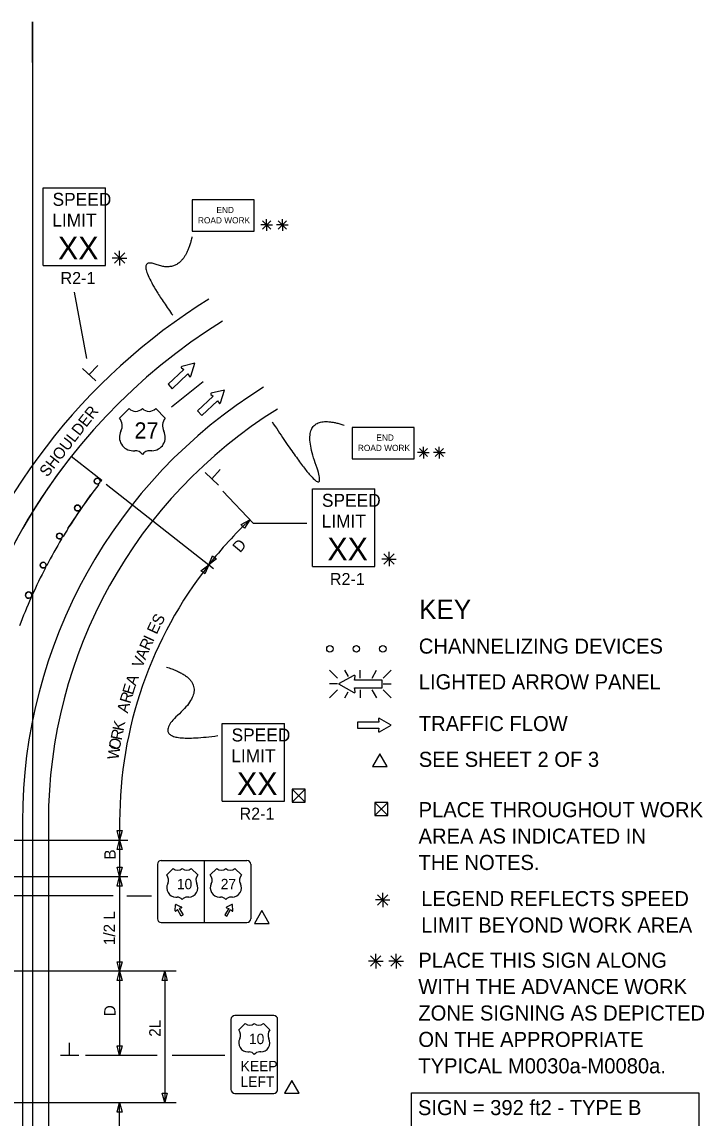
# Model space of a CAD drawing. Extents: x 16519 to 19508, y 5743 to 6974.
# Drawn here: x 16998 to 17419, y 6297 to 6974 of the extents above; entities that cross this region are included whole.
import ezdxf

# ---------------------------------------------------------------- set-up
doc = ezdxf.new("R2010")
doc.units = 0
for name, color, linetype in [('ALI_LEGAL_EX', 7, 'Continuous'), ('MT_SCRATCH_LEVEL_A', 7, 'Continuous'), ('MT_SCRATCH_LEVEL_E', 7, 'Continuous'), ('PAVT_EDGE_EX', 7, 'Continuous'), ('TRAFFIC_SIGNS_PR', 7, 'Continuous'), ('TYPICAL_EX', 7, 'Continuous'), ('TYPICAL_TEXT_DIMEN_EX', 7, 'Continuous'), ('TYPICAL_TEXT_DIMEN_PR', 7, 'Continuous')]:
    doc.layers.add(name, color=color, linetype=linetype)

msp = doc.modelspace()

# ---------------------------------------------------------------- linework, layer by layer
at = {"layer": 'ALI_LEGAL_EX'}
for p, q in [((17004.68, 6974.12), (17004.68, 6155.98)), ((17004.68, 6922.21), (17004.68, 6058.3))]:
    msp.add_line(p, q, dxfattribs=at)
for points in [[(17004.68, 6949.12), (17004.68, 6974.12)], [(17090.52, 6736.48), (17109.97, 6752.18)], [(17026.51, 6661.47), (17040.64, 6682.1)]]:
    msp.add_lwpolyline(points, dxfattribs=at)
at = {"layer": 'MT_SCRATCH_LEVEL_A'}
for points in [[(17047.4, 6690.98), (17028.55, 6705.83)], [(17045.52, 6688.56), (17045.06, 6688.91)], [(17046.41, 6690.77), (17047.26, 6690.79)], [(17033.55, 6672.09), (17033.12, 6672.38)], [(17034.27, 6674.06), (17034.69, 6673.76)], [(17022.59, 6654.94), (17022.2, 6655.17)], [(17023.15, 6656.76), (17023.54, 6656.52)], [(17013.08, 6638.82), (17013.44, 6638.63)], [(17012.67, 6637.16), (17012.32, 6637.35)], [(17003.81, 6618.76), (17003.65, 6618.83)], [(17004.31, 6620.31), (17004.48, 6620.24)]]:
    msp.add_lwpolyline(points, dxfattribs=at)
for centre, radius, start, end in [((17314.45, 6480.53), 364, 141.75977, 180), ((17044.61, 6690.66), 1.8, 3.5129, 180), ((17314.45, 6480.53), 340, 142.2759, 145.36613), ((17044.61, 6690.66), 1.8, 180, 284.5518), ((17314.45, 6480.53), 340, 141.75977, 141.79923), ((17314.45, 6480.53), 340, 145.70741, 148.82754), ((17032.47, 6674.06), 1.8, 0, 180), ((17032.47, 6674.06), 1.8, 180, 291.41483), ((17021.35, 6656.76), 1.8, 0, 180), ((17314.45, 6480.53), 340, 149.13833, 152.28953), ((17021.35, 6656.76), 1.8, 180, 298.27665), ((17011.28, 6638.82), 1.8, 0, 180), ((17011.28, 6638.82), 1.8, 180, 305.13736), ((17314.45, 6480.53), 340, 152.56868, 155.7382), ((17314.45, 6480.53), 340, 156.0121, 159.20322), ((17002.31, 6620.31), 2, 0, 180), ((17002.31, 6620.31), 2, 180, 312.02419)]:
    msp.add_arc(centre, radius, start, end, dxfattribs=at)
at = {"layer": 'MT_SCRATCH_LEVEL_E'}
for p, q in [((17096.59, 6760.6), (17098.04, 6759.51)), ((17104.85, 6763.37), (17096.76, 6761.41)), ((17102.41, 6755.39), (17104.85, 6763.37)), ((17098.04, 6759.51), (17088.37, 6750.45)), ((17090.92, 6747.72), (17100.6, 6756.78)), ((17100.6, 6756.78), (17101.58, 6755.27)), ((17088.37, 6750.45), (17090.92, 6747.72)), ((17123.06, 6746.9), (17114.96, 6744.94)), ((17120.61, 6738.92), (17123.06, 6746.9)), ((17116.24, 6743.04), (17106.57, 6733.98)), ((17109.13, 6731.25), (17118.8, 6740.31)), ((17114.79, 6744.12), (17116.24, 6743.04)), ((17118.8, 6740.31), (17119.78, 6738.8)), ((17106.57, 6733.98), (17109.13, 6731.25)), ((17218.08, 6543.71), (17218.4, 6541.94)), ((17226.01, 6540.09), (17218.77, 6544.2)), ((17218.4, 6541.94), (17205.14, 6541.94)), ((17205.14, 6541.94), (17205.14, 6538.19)), ((17205.14, 6538.19), (17218.4, 6538.19)), ((17218.4, 6538.19), (17218.08, 6536.42)), ((17218.77, 6535.94), (17226.01, 6540.09))]:
    msp.add_line(p, q, dxfattribs=at)
for centre, start, end in [((17096.87, 6760.96), 103.58205, 233.12102), ((17101.96, 6755.54), 213.1934, 342.93033), ((17115.08, 6744.49), 103.58205, 233.12102), ((17120.17, 6739.07), 213.1934, 342.93033), ((17218.54, 6543.79), 60.42484, 189.96381), ((17218.54, 6536.35), 170.03619, 299.77312)]:
    msp.add_arc(centre, 0.463, start, end, dxfattribs=at)
at = {"layer": 'PAVT_EDGE_EX'}
for p, q in [((16998.45, 6480.53), (16998.45, 6125.9)), ((17014.45, 6480.53), (17014.45, 6125.9))]:
    msp.add_line(p, q, dxfattribs=at)
for radius, start, end in [(380, 121.93275, 163.04831), (364, 121.93275, 180), (316, 121.93275, 180), (300, 121.93275, 180), (300, 180, 180.00000277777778)]:
    msp.add_arc((17314.45, 6480.53), radius, start, end, dxfattribs=at)
at = {"layer": 'TRAFFIC_SIGNS_PR'}
for p, q in [((17011.27, 6871.74), (17049.67, 6871.74)), ((17011.27, 6823.74), (17011.27, 6871.74)), ((17049.67, 6823.74), (17049.67, 6871.74)), ((17011.27, 6823.74), (17049.67, 6823.74)), ((17177.5, 6685.93), (17215.9, 6685.93)), ((17177.5, 6637.93), (17177.5, 6685.93)), ((17215.9, 6637.93), (17215.9, 6685.93)), ((17177.5, 6637.93), (17215.9, 6637.93)), ((17187.86, 6573.9), (17192.79, 6568.96)), ((17199.62, 6570.07), (17197.41, 6573.9)), ((17206.94, 6568.96), (17206.94, 6573.9)), ((17214.17, 6568.96), (17217.02, 6573.9)), ((17221.09, 6568.96), (17226.03, 6573.9)), ((17192.79, 6565.41), (17187.86, 6565.41)), ((17221.09, 6565.41), (17226.03, 6565.41)), ((17187.86, 6556.92), (17192.79, 6561.85)), ((17197.37, 6556.92), (17199.48, 6560.58)), ((17206.94, 6561.85), (17206.94, 6556.92)), ((17217.07, 6556.92), (17214.22, 6561.85)), ((17221.09, 6561.85), (17226.03, 6556.91)), ((17121.73, 6541.08), (17160.13, 6541.08)), ((17121.73, 6493.08), (17121.73, 6541.08)), ((17160.13, 6493.08), (17160.13, 6541.08)), ((17121.73, 6493.08), (17160.13, 6493.08)), ((17084.13, 6456.52), (17136.93, 6456.52)), ((17110.53, 6456.52), (17110.53, 6418.12)), ((17081.73, 6454.12), (17081.73, 6420.52)), ((17139.33, 6454.12), (17139.33, 6420.52)), ((17092.71, 6425.47), (17092.99, 6429.09)), ((17093.36, 6429.3), (17096.64, 6427.74)), ((17127.69, 6429.3), (17124.42, 6427.74)), ((17128.35, 6425.47), (17128.07, 6429.09)), ((17084.13, 6418.12), (17136.93, 6418.12)), ((17127.14, 6358.32), (17127.14, 6315.12)), ((17153.54, 6360.72), (17129.54, 6360.72)), ((17155.94, 6315.12), (17155.94, 6358.32)), ((17129.54, 6312.72), (17153.54, 6312.72))]:
    msp.add_line(p, q, dxfattribs=at)
for points in [[(17103.15, 6845), (17141.55, 6845), (17141.55, 6864.2), (17103.15, 6864.2)], [(17201.84, 6704.49), (17240.24, 6704.49), (17240.24, 6723.69), (17201.84, 6723.69)]]:
    msp.add_lwpolyline(points, close=True, dxfattribs=at)
for points in [[(17202.87, 6570.68), (17193.58, 6565.41), (17202.87, 6560.09)], [(17203.74, 6560.71), (17203.34, 6562.98), (17220.35, 6562.98), (17220.35, 6567.78), (17203.34, 6567.78), (17203.74, 6570.06)], [(17096.6, 6427.25), (17095.19, 6426.86), (17097.71, 6422.88), (17096.38, 6422.12), (17094.19, 6426.29), (17093.15, 6425.26)], [(17124.46, 6427.25), (17125.87, 6426.86), (17123.35, 6422.88), (17124.68, 6422.12), (17126.87, 6426.29), (17127.91, 6425.26)]]:
    msp.add_lwpolyline(points, dxfattribs=at)
for centre, radius in [((17044.61, 6690.66), 1.8), ((17032.47, 6674.06), 1.8), ((17021.35, 6656.76), 1.8), ((17011.28, 6638.82), 1.8), ((17002.31, 6620.31), 2), ((17188.2, 6587.09), 2), ((17204.5, 6587.09), 2), ((17220.8, 6587.09), 2)]:
    msp.add_circle(centre, radius, dxfattribs=at)
for centre, radius, start, end in [((17203.16, 6570.16), 0.598, 350.73078, 118.89165), ((17203.15, 6560.61), 0.597, 241.48329, 9.95933), ((17084.13, 6454.12), 2.4, 90, 180), ((17084.13, 6454.12), 2.4, 90, 180), ((17136.93, 6454.12), 2.4, 0, 90), ((17093.25, 6429.07), 0.26, 64.48226, 175.51774), ((17127.81, 6429.07), 0.26, 4.48226, 115.51774), ((17092.97, 6425.45), 0.26, 175.51775, 314.01151), ((17096.53, 6427.5), 0.26, 285.9885, 64.48226), ((17124.53, 6427.5), 0.26, 115.51774, 254.0115), ((17128.09, 6425.45), 0.26, 225.98849, 4.48225), ((17084.13, 6420.52), 2.4, 180, 270), ((17136.93, 6420.52), 2.4, 270, 0), ((17129.54, 6358.32), 2.4, 90, 180), ((17153.54, 6358.32), 2.4, 0, 90), ((17129.54, 6315.12), 2.4, 180, 270), ((17153.54, 6315.12), 2.4, 270, 0)]:
    msp.add_arc(centre, radius, start, end, dxfattribs=at)
at = {"layer": 'TYPICAL_EX'}
for p, q in [((17058.33, 6729.51), (17064.22, 6735.4)), ((17086.62, 6729.51), (17080.73, 6735.4)), ((17066.57, 6709.45), (17067.75, 6709.45)), ((17078.38, 6709.45), (17077.2, 6709.45)), ((17087.48, 6447.52), (17091.48, 6451.52)), ((17106.68, 6447.52), (17102.68, 6451.52)), ((17114.38, 6447.52), (17118.38, 6451.52)), ((17133.58, 6447.52), (17129.58, 6451.52)), ((17093.07, 6433.91), (17093.87, 6433.91)), ((17101.09, 6433.91), (17100.29, 6433.91)), ((17119.97, 6433.91), (17120.77, 6433.91)), ((17127.99, 6433.91), (17127.19, 6433.91)), ((17131.94, 6351.92), (17135.94, 6355.92)), ((17151.14, 6351.92), (17147.14, 6355.92)), ((17137.54, 6338.31), (17138.34, 6338.31)), ((17145.55, 6338.31), (17144.75, 6338.31))]:
    msp.add_line(p, q, dxfattribs=at)
for centre, radius, start, end in [((17068.35, 6739.69), 5.96, 226.14041, 313.85958), ((17076.6, 6739.69), 5.96, 226.14042, 313.85959), ((17052.74, 6724.78), 7.31, 333.09768, 40.19361), ((17092.21, 6724.78), 7.31, 139.80639, 206.90233), ((17066.59, 6717.69), 8.24, 152.6698, 269.90132), ((17078.36, 6717.69), 8.24, 270.09868, 27.3302), ((17067.77, 6703.54), 5.91, 37.1038, 90.13853), ((17077.19, 6703.54), 5.91, 89.86147, 142.8962), ((17094.28, 6454.43), 4.04, 226.14041, 313.85958), ((17099.88, 6454.43), 4.04, 226.14042, 313.85959), ((17121.18, 6454.43), 4.04, 226.14041, 313.85958), ((17126.78, 6454.43), 4.04, 226.14042, 313.85959), ((17083.69, 6444.31), 4.96, 333.09768, 40.19361), ((17093.08, 6439.5), 5.59, 152.6698, 269.90132), ((17101.08, 6439.5), 5.59, 270.09868, 27.3302), ((17110.47, 6444.31), 4.96, 139.80639, 206.90233), ((17110.59, 6444.31), 4.96, 333.09768, 40.19361), ((17119.98, 6439.5), 5.59, 152.6698, 269.90132), ((17127.97, 6439.5), 5.59, 270.09868, 27.3302), ((17137.37, 6444.31), 4.96, 139.80639, 206.90233), ((17093.88, 6429.9), 4.01, 37.1038, 90.13853), ((17100.28, 6429.9), 4.01, 89.86147, 142.8962), ((17120.78, 6429.9), 4.01, 37.1038, 90.13853), ((17127.17, 6429.9), 4.01, 89.86147, 142.8962), ((17138.74, 6358.83), 4.04, 226.14041, 313.85958), ((17144.34, 6358.83), 4.04, 226.14042, 313.85959), ((17128.15, 6348.71), 4.96, 333.09768, 40.19361), ((17154.94, 6348.71), 4.96, 139.80639, 206.90233), ((17137.55, 6343.9), 5.59, 152.6698, 269.90132), ((17145.54, 6343.9), 5.59, 270.09868, 27.3302), ((17138.35, 6334.3), 4.01, 37.1038, 90.13853), ((17144.74, 6334.3), 4.01, 89.86147, 142.8962)]:
    msp.add_arc(centre, radius, start, end, dxfattribs=at)
at = {"layer": 'TYPICAL_TEXT_DIMEN_EX'}
msp.add_lwpolyline([(17238.46, 6313.09), (17415.73, 6313.09), (17415.73, 6227.77), (17238.46, 6227.77)], close=True, dxfattribs=at)
at = {"layer": 'TYPICAL_TEXT_DIMEN_PR'}
for p, q in [((17149.1, 6848.82), (17145.47, 6848.82)), ((17146.55, 6851.37), (17151.65, 6846.27)), ((17151.65, 6851.37), (17146.55, 6846.27)), ((17149.1, 6848.82), (17149.1, 6852.38)), ((17149.1, 6848.82), (17151.65, 6848.82)), ((17149.1, 6848.82), (17152.68, 6848.82)), ((17149.1, 6848.82), (17149.1, 6845.22)), ((17158.85, 6848.82), (17155.22, 6848.82)), ((17156.3, 6851.37), (17161.4, 6846.27)), ((17161.4, 6851.37), (17156.3, 6846.27)), ((17158.85, 6848.82), (17158.85, 6852.38)), ((17158.85, 6848.82), (17161.4, 6848.82)), ((17158.85, 6848.82), (17162.43, 6848.82)), ((17158.85, 6848.82), (17158.85, 6845.22)), ((17058.46, 6828.35), (17053.93, 6828.35)), ((17061.65, 6831.54), (17055.27, 6825.16)), ((17055.28, 6831.54), (17061.65, 6825.16)), ((17058.46, 6828.35), (17058.46, 6832.81)), ((17058.46, 6828.35), (17061.65, 6828.35)), ((17058.46, 6828.35), (17062.94, 6828.35)), ((17058.46, 6828.35), (17058.46, 6823.85)), ((17038.28, 6766.41), (17030.49, 6807.29)), ((17043.83, 6752.57), (17035.58, 6760.22)), ((17039.7, 6756.39), (17045, 6762.1)), ((17245.95, 6708.31), (17242.32, 6708.31)), ((17243.4, 6710.86), (17248.5, 6705.76)), ((17248.5, 6710.86), (17243.4, 6705.76)), ((17245.95, 6708.31), (17245.95, 6711.87)), ((17245.95, 6708.31), (17248.5, 6708.31)), ((17245.95, 6708.31), (17249.53, 6708.31)), ((17245.95, 6708.31), (17245.95, 6704.71)), ((17255.69, 6708.31), (17252.07, 6708.31)), ((17253.14, 6710.86), (17258.24, 6705.76)), ((17258.24, 6710.86), (17253.14, 6705.76)), ((17255.69, 6708.31), (17255.69, 6711.87)), ((17255.69, 6708.31), (17258.24, 6708.31)), ((17255.69, 6708.31), (17259.28, 6708.31)), ((17255.69, 6708.31), (17255.69, 6704.71)), ((17119.38, 6688.23), (17111.13, 6695.89)), ((17115.25, 6692.06), (17120.55, 6697.77)), ((17050.11, 6688.84), (17116.38, 6636.62)), ((17122.13, 6684.37), (17140.75, 6664.64)), ((17133.42, 6663.86), (17138.77, 6666.74)), ((17138.77, 6666.74), (17135.58, 6661.57)), ((17134.5, 6662.71), (17133.42, 6663.86)), ((17135.58, 6661.57), (17134.5, 6662.71)), ((17140.75, 6664.64), (17173.95, 6664.64)), ((17221.5, 6645.73), (17227.87, 6639.36)), ((17227.87, 6645.73), (17221.5, 6639.36)), ((17224.69, 6642.55), (17224.69, 6647)), ((17108.52, 6635.35), (17113.38, 6638.99)), ((17113.38, 6638.99), (17110.98, 6633.41)), ((17113.38, 6638.99), (17115.77, 6644.56)), ((17118.24, 6642.62), (17113.38, 6638.99)), ((17115.77, 6644.56), (17117.01, 6643.59)), ((17117.01, 6643.59), (17118.24, 6642.62)), ((17224.69, 6642.55), (17220.15, 6642.55)), ((17224.69, 6642.55), (17227.87, 6642.55)), ((17224.69, 6642.55), (17229.16, 6642.55)), ((17224.69, 6642.55), (17224.69, 6638.05)), ((17109.75, 6634.38), (17108.52, 6635.35)), ((17110.98, 6633.41), (17109.75, 6634.38)), ((17004.96, 6621.31), (17003.13, 6622.14)), ((17164.92, 6500.4), (17172.92, 6492.4)), ((17164.92, 6492.4), (17172.92, 6500.4)), ((17215.92, 6492.31), (17223.92, 6484.31)), ((17215.92, 6484.31), (17223.92, 6492.31)), ((17058.45, 6480.53), (17058.45, 6469.09)), ((16977.64, 6469.09), (17063.45, 6469.09)), ((17058.45, 6469.09), (17056.88, 6474.95)), ((17056.88, 6474.95), (17058.45, 6474.95)), ((17056.88, 6463.22), (17058.45, 6469.09)), ((17058.45, 6474.95), (17060.02, 6474.95)), ((17060.02, 6474.95), (17058.45, 6469.09)), ((17058.45, 6469.09), (17058.45, 6446.53)), ((17058.45, 6469.09), (17060.02, 6463.22)), ((17058.45, 6463.22), (17056.88, 6463.22)), ((17060.02, 6463.22), (17058.45, 6463.22)), ((17058.45, 6446.53), (17056.88, 6452.39)), ((17056.88, 6452.39), (17058.45, 6452.39)), ((17058.45, 6452.39), (17060.02, 6452.39)), ((17060.02, 6452.39), (17058.45, 6446.53)), ((16977.64, 6446.53), (17063.45, 6446.53)), ((17056.88, 6440.67), (17058.45, 6446.53)), ((17058.45, 6446.53), (17058.45, 6388.14)), ((17058.45, 6446.53), (17060.02, 6440.67)), ((17058.45, 6440.67), (17056.88, 6440.67)), ((17060.02, 6440.67), (17058.45, 6440.67)), ((17217.57, 6435.33), (17223.94, 6428.95)), ((17223.94, 6435.33), (17217.57, 6428.95)), ((17220.75, 6432.14), (17220.75, 6436.59)), ((17054.35, 6434.68), (16990.46, 6434.68)), ((17062.85, 6434.68), (17078.05, 6434.68)), ((17220.75, 6432.14), (17216.22, 6432.14)), ((17220.75, 6432.14), (17223.94, 6432.14)), ((17220.75, 6432.14), (17225.23, 6432.14)), ((17220.75, 6432.14), (17220.75, 6427.64)), ((17213.28, 6397.51), (17219.66, 6391.13)), ((17219.66, 6397.51), (17213.28, 6391.13)), ((17216.47, 6394.32), (17216.47, 6398.78)), ((17225.84, 6397.51), (17232.21, 6391.13)), ((17232.21, 6397.51), (17225.84, 6391.13)), ((17229.02, 6394.32), (17229.02, 6398.78)), ((17093.24, 6388.14), (16977.64, 6388.14)), ((17058.45, 6388.14), (17056.88, 6394)), ((17056.88, 6394), (17058.45, 6394)), ((17056.88, 6382.28), (17058.45, 6388.14)), ((17058.45, 6394), (17060.02, 6394)), ((17060.02, 6394), (17058.45, 6388.14)), ((17058.45, 6388.14), (17060.02, 6382.28)), ((17058.45, 6388.14), (17058.45, 6336.14)), ((17084.68, 6382.28), (17086.25, 6388.14)), ((17086.25, 6388.14), (17086.25, 6307.03)), ((17086.25, 6388.14), (17087.82, 6382.28)), ((17216.47, 6394.32), (17211.94, 6394.32)), ((17216.47, 6394.32), (17219.66, 6394.32)), ((17216.47, 6394.32), (17220.95, 6394.32)), ((17216.47, 6394.32), (17216.47, 6389.82)), ((17229.02, 6394.32), (17224.49, 6394.32)), ((17229.02, 6394.32), (17232.21, 6394.32)), ((17229.02, 6394.32), (17233.5, 6394.32)), ((17229.02, 6394.32), (17229.02, 6389.82)), ((17058.45, 6382.28), (17056.88, 6382.28)), ((17060.02, 6382.28), (17058.45, 6382.28)), ((17086.25, 6382.28), (17084.68, 6382.28)), ((17087.82, 6382.28), (17086.25, 6382.28)), ((17027.57, 6336.14), (17027.57, 6343.92)), ((17058.45, 6336.14), (17056.88, 6342)), ((17056.88, 6342), (17058.45, 6342)), ((17058.45, 6342), (17060.02, 6342)), ((17060.02, 6342), (17058.45, 6336.14)), ((17033.2, 6336.14), (17021.95, 6336.14)), ((17081.61, 6336.14), (17037.45, 6336.14)), ((17123.26, 6336.14), (17090.76, 6336.14)), ((16953.49, 6307.03), (17093.24, 6307.03)), ((17056.88, 6301.17), (17058.45, 6307.03)), ((17058.45, 6278.47), (17058.45, 6307.03)), ((17058.45, 6307.03), (17060.02, 6301.17)), ((17086.25, 6307.03), (17084.68, 6312.89)), ((17084.68, 6312.89), (17086.25, 6312.89)), ((17086.25, 6312.89), (17087.82, 6312.89)), ((17087.82, 6312.89), (17086.25, 6307.03)), ((17058.45, 6301.17), (17056.88, 6301.17)), ((17060.02, 6301.17), (17058.45, 6301.17))]:
    msp.add_line(p, q, dxfattribs=at)
for points in [[(17219.07, 6522.38), (17214.55, 6514.54), (17223.6, 6514.54)], [(17164.92, 6500.4), (17164.92, 6492.4), (17172.92, 6492.4), (17172.92, 6500.4)], [(17215.92, 6492.31), (17215.92, 6484.31), (17223.92, 6484.31), (17223.92, 6492.31)], [(17146.22, 6425.5), (17141.69, 6417.66), (17150.74, 6417.66)], [(17164.71, 6320.68), (17160.19, 6312.84), (17169.24, 6312.84)]]:
    msp.add_lwpolyline(points, close=True, dxfattribs=at)
for start, end in [(133.33402, 141.75968), (141.75968, 180)]:
    msp.add_arc((17314.45, 6480.53), 256, start, end, dxfattribs=at)
for points in [[(17103.08, 6841.44), (17097.91, 6817.84), (17064.24, 6830.87), (17091.19, 6793)], [(17152.53, 6727.28), (17190.76, 6669.11), (17167.55, 6734.81), (17196.9, 6725.23)], [(17087.4, 6575.84), (17116.93, 6566.68), (17073.34, 6527.21), (17119.04, 6533.55)]]:
    msp.add_open_spline(points, degree=2, dxfattribs=at)

# ---------------------------------------------------------------- texts
at = {"layer": 'TRAFFIC_SIGNS_PR'}
for s, height, p in [('SPEED', 8, (17017.04, 6860.6)), ('LIMIT', 8, (17016.88, 6847.8)), ('END', 3.831, (17118.15, 6856.13)), ('ROAD WORK', 3.831, (17106.76, 6849.74)), ('XX', 14.031, (17020.39, 6827.49)), ('R2-1', 7.44, (17021.95, 6812.3)), ('END', 3.831, (17216.84, 6715.61)), ('ROAD WORK', 3.831, (17205.45, 6709.23)), ('SPEED', 8, (17183.26, 6674.79)), ('LIMIT', 8, (17183.1, 6661.99)), ('XX', 14.031, (17186.61, 6641.69)), ('R2-1', 7.44, (17188.17, 6626.49)), ('SPEED', 8, (17127.5, 6529.94)), ('LIMIT', 8, (17127.34, 6517.14)), ('XX', 14.031, (17130.84, 6496.84)), ('R2-1', 7.44, (17132.41, 6481.64)), ('10', 6.4, (17093.74, 6438.72)), ('27', 6.4, (17120.81, 6438.72)), ('10', 6.4, (17138.2, 6343.12)), ('KEEP', 6.4, (17133.08, 6326.32)), ('LEFT', 6.4, (17132.99, 6316.72))]:
    msp.add_text(s, height=height, dxfattribs=at).set_placement(p)
at = {"layer": 'TYPICAL_EX'}
msp.add_text('27', height=10, dxfattribs=at).set_placement((17067.59, 6716.93))
at = {"layer": 'TYPICAL_TEXT_DIMEN_EX'}
for s, height, p in [('KEY', 12, (17243.23, 6605.49)), ('CHANNELIZING DEVICES', 9.3, (17243.04, 6584.15)), ('LIGHTED ARROW PANEL', 9.3, (17243.04, 6562.1)), ('TRAFFIC FLOW', 9.3, (17243.04, 6536.3)), ('SEE SHEET 2 OF 3', 9.3, (17243.04, 6514.25)), ('PLACE THROUGHOUT WORK', 9.3, (17242.9, 6483.19)), ('AREA AS INDICATED IN', 9.3, (17242.9, 6466.89)), ('THE NOTES.', 9.3, (17242.9, 6450.59)), ('LEGEND REFLECTS SPEED', 9.3, (17244.52, 6428.27)), ('LIMIT BEYOND WORK AREA', 9.3, (17244.52, 6411.97)), ('PLACE THIS SIGN ALONG', 9.3, (17242.76, 6390.26)), ('WITH THE ADVANCE WORK', 9.3, (17242.76, 6373.96)), ('ZONE SIGNING AS DEPICTED', 9.3, (17242.76, 6357.66)), ('ON THE APPROPRIATE', 9.3, (17242.76, 6341.36)), ('TYPICAL M0030a-M0080a.', 9.3, (17242.76, 6325.06)), ('SIGN = 392 ft2 - TYPE B', 9.3, (17242.51, 6299.27))]:
    msp.add_text(s, height=height, dxfattribs=at).set_placement(p)
at = {"layer": 'TYPICAL_TEXT_DIMEN_PR'}
for s, rotation, p in [('SHOULDER', 52.01843, (17013.81, 6692.73)), ('D', 50, (17132.79, 6646.01)), ('S', 62.49737, (17083.98, 6600.91)), ('E', 65.17719, (17081.28, 6595.61)), ('R', 65.17719, (17076.62, 6585.54)), ('I', 65.17719, (17079.13, 6590.96)), ('A', 67.85702, (17074.34, 6579.94)), ('V', 67.85702, (17072.25, 6574.78)), ('E', 73.21667, (17066.62, 6558.32)), ('A', 70.53685, (17068.37, 6563.9)), ('R', 73.21667, (17064.99, 6552.92)), ('A', 75.8965, (17063.42, 6547.08)), ('R', 78.57633, (17059.63, 6530.32)), ('K', 78.57633, (17060.77, 6535.95)), ('O', 81.25615, (17058.54, 6524.36)), ('W', 81.25615, (17057.62, 6518.33)), ('B', 90, (17056.01, 6457.04)), ('1/2 L', 90, (17055.59, 6404.27)), ('D', 90, (17055.89, 6360.36)), ('2L', 90, (17083.69, 6347.64))]:
    msp.add_text(s, height=7, rotation=rotation, dxfattribs=at).set_placement(p)

doc.saveas('drawing.dxf')
